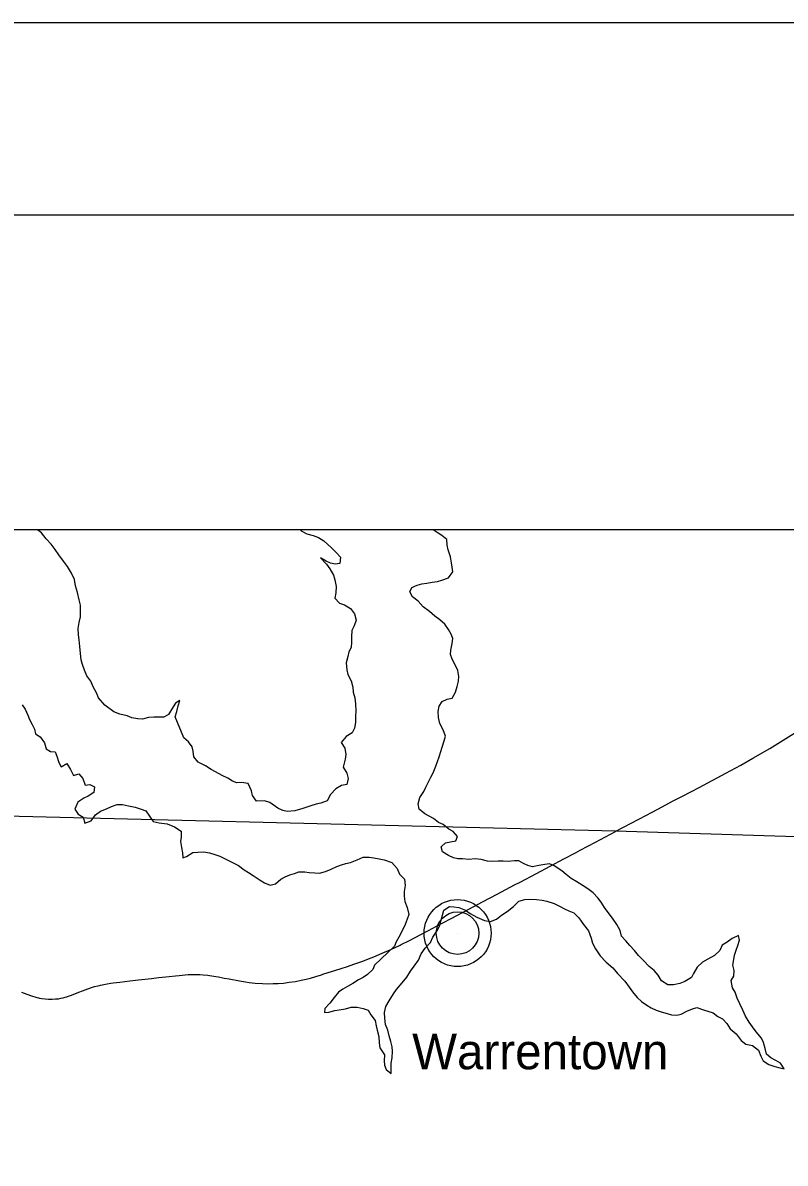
# Model space of a CAD drawing. Extents: x -29.6 to 34, y 0 to 22.
# Drawn here: x 8.82 to 10.805, y 19.03 to 22 of the extents above; entities that cross this region are included whole.
import ezdxf

# ---------------------------------------------------------------- set-up
doc = ezdxf.new("R2010")
doc.units = 0
for name, color, linetype in [('GM_X_Major_Lake', 7, 'Continuous'), ('GM_X_Township', 7, 'Continuous'), ('GM_X_Unincorporated', 7, 'Continuous'), ('GM_X_Unincorporated_Location', 7, 'Continuous'), ('GM_X_Unincorporated_Text', 7, 'Continuous'), ('GM_X_US_Route', 7, 'Continuous'), ('SH_Border', 7, 'Continuous'), ('SH_Cut_Line', 7, 'Continuous'), ('SH_Text', 7, 'Continuous')]:
    doc.layers.add(name, color=color, linetype=linetype)

msp = doc.modelspace()

# ---------------------------------------------------------------- linework, layer by layer
at = {"layer": 'GM_X_Major_Lake'}
for points in [[(9.2387, 20.1379), (9.2161, 20.1924), (9.2209, 20.2062), (9.2243, 20.2208), (9.2291, 20.2355), (9.2172, 20.2279), (9.2071, 20.2118), (9.1988, 20.1985), (9.1869, 20.1917), (9.1749, 20.1921), (9.1607, 20.1915), (9.1474, 20.1905), (9.1315, 20.1864), (9.1196, 20.1872), (9.104, 20.1902), (9.0912, 20.1955), (9.0721, 20.1998), (9.057, 20.2059), (9.0334, 20.2226), (9.0173, 20.242), (9.0119, 20.2553), (9.0029, 20.2704), (8.9966, 20.2854), (8.9864, 20.2996), (8.9805, 20.3142), (8.9751, 20.3284), (8.9719, 20.3412), (8.9696, 20.3576), (8.9681, 20.3758), (8.9662, 20.3927), (8.9652, 20.406), (8.9642, 20.4224), (8.9664, 20.4385), (8.9698, 20.4531), (8.9696, 20.4833), (8.9668, 20.4975), (8.9618, 20.5162), (8.9568, 20.5339), (8.9541, 20.5503), (8.9469, 20.5667), (8.9361, 20.5844), (8.9258, 20.5981), (8.9138, 20.6144), (8.9044, 20.6281), (8.8937, 20.6418), (8.8803, 20.6564), (8.8682, 20.6714), (8.8577, 20.6798)], [(9.5426, 20.6798), (9.5442, 20.6773), (9.5594, 20.6694), (9.5758, 20.6646), (9.5901, 20.6594), (9.6039, 20.6511), (9.6232, 20.6326), (9.6357, 20.6203), (9.6469, 20.6084), (9.6453, 20.5919), (9.6329, 20.59), (9.6213, 20.5926), (9.6093, 20.5983), (9.595, 20.6066)], [(9.9251, 20.2383), (9.9375, 20.2411), (9.9463, 20.2567), (9.9506, 20.2719), (9.9545, 20.2852), (9.9552, 20.2972), (9.9529, 20.3136), (9.9465, 20.326), (9.9375, 20.3428), (9.9334, 20.3548), (9.9342, 20.3664), (9.9376, 20.3837), (9.9397, 20.3962), (9.9351, 20.4077), (9.9279, 20.4201), (9.9185, 20.4338), (9.9055, 20.4452), (9.8925, 20.4549), (9.8791, 20.4668), (9.8626, 20.4791), (9.8496, 20.4941), (9.8348, 20.5051), (9.8271, 20.5183), (9.8328, 20.5295), (9.8465, 20.5358), (9.8589, 20.5386), (9.8722, 20.5409), (9.886, 20.5433), (9.8997, 20.5452), (9.9112, 20.5488), (9.928, 20.5547), (9.9395, 20.5699), (9.938, 20.5819), (9.9361, 20.5939), (9.9338, 20.609), (9.9274, 20.6272), (9.9246, 20.64), (9.9236, 20.6547), (9.9106, 20.6652), (9.8986, 20.6722), (9.888, 20.6798)], [(9.595, 20.6066), (9.6103, 20.5898), (9.6192, 20.5784), (9.6287, 20.5616), (9.6319, 20.5496), (9.6356, 20.5318), (9.6349, 20.5158), (9.6324, 20.5012), (9.6445, 20.4884), (9.6578, 20.484), (9.673, 20.4748), (9.6834, 20.4607), (9.6875, 20.4447), (9.6827, 20.4296), (9.6766, 20.4175), (9.6755, 20.4011), (9.6756, 20.3873), (9.6748, 20.3735), (9.6691, 20.3619), (9.6657, 20.3499), (9.6619, 20.3334), (9.6634, 20.3148), (9.6657, 20.3032), (9.6747, 20.286), (9.6793, 20.2696), (9.6803, 20.2567), (9.6844, 20.2416), (9.6864, 20.2265), (9.6865, 20.207), (9.6858, 20.195), (9.6864, 20.1781), (9.6838, 20.1634), (9.6777, 20.1509), (9.6618, 20.141), (9.6491, 20.1253), (9.6586, 20.1112), (9.6605, 20.0943), (9.6593, 20.0823), (9.6541, 20.0618), (9.6632, 20.0454), (9.6673, 20.0321), (9.6639, 20.0161), (9.6492, 20.0133), (9.6347, 20.0052), (9.6206, 19.9904), (9.6119, 19.9739), (9.5959, 19.968), (9.584, 19.9652), (9.5694, 19.9611), (9.549, 19.9534), (9.5282, 19.9479), (9.5082, 19.9459), (9.4966, 19.9489), (9.4837, 19.955), (9.4627, 19.9691), (9.4489, 19.9739), (9.4285, 19.9732), (9.4177, 19.9878), (9.4149, 19.9998), (9.4063, 20.0193), (9.389, 20.0218), (9.3774, 20.0208), (9.3654, 20.0247), (9.3538, 20.0331), (9.3391, 20.0396), (9.3212, 20.0497), (9.3101, 20.0558), (9.2953, 20.0646), (9.2766, 20.0742), (9.2654, 20.0883), (9.263, 20.103), (9.2611, 20.1145), (9.2508, 20.1278), (9.2387, 20.1379)], [(10.6686, 19.5462), (10.6707, 19.5609), (10.6728, 19.572), (10.6776, 19.585), (10.6819, 19.597), (10.6858, 19.6113), (10.683, 19.6228), (10.6671, 19.6156), (10.6534, 19.6057), (10.6406, 19.5976), (10.6345, 19.5837), (10.6209, 19.5707), (10.6036, 19.5617), (10.5895, 19.5536), (10.5759, 19.5406), (10.5663, 19.5245), (10.5606, 19.5133), (10.5434, 19.5034), (10.5305, 19.4979), (10.5137, 19.4947), (10.499, 19.4946), (10.483, 19.5051), (10.4744, 19.5201), (10.4636, 19.5316), (10.4511, 19.5426), (10.4349, 19.5589), (10.4233, 19.5713), (10.4121, 19.5836), (10.3999, 19.5973), (10.3901, 19.6088), (10.3789, 19.6211), (10.3752, 19.6358), (10.3666, 19.6517), (10.3549, 19.6681), (10.3436, 19.6831), (10.3342, 19.6959), (10.3256, 19.7096), (10.3171, 19.7215), (10.305, 19.7343), (10.2907, 19.7444), (10.2791, 19.7528), (10.2625, 19.7624), (10.2474, 19.7712), (10.2344, 19.7822), (10.2232, 19.7914), (10.2031, 19.8046), (10.1915, 19.8094), (10.1791, 19.808), (10.1636, 19.8052), (10.1467, 19.8019), (10.1347, 19.8054), (10.1231, 19.8102), (10.1111, 19.8172), (10.1, 19.8171), (10.0835, 19.8161), (10.0702, 19.8168), (10.0573, 19.8167), (10.0405, 19.8161), (10.0294, 19.8169), (10.0133, 19.8208), (9.9978, 19.8229), (9.9814, 19.8214), (9.9649, 19.8226), (9.9525, 19.8225), (9.9414, 19.8255), (9.9284, 19.8312), (9.9128, 19.8413), (9.9087, 19.8541), (9.9201, 19.864), (9.933, 19.8668), (9.9472, 19.8696), (9.952, 19.8807), (9.9407, 19.8935), (9.9291, 19.9001), (9.9144, 19.9124), (9.9023, 19.9172), (9.8889, 19.9282), (9.8778, 19.9339), (9.8662, 19.94), (9.8514, 19.9519), (9.849, 19.9661), (9.8533, 19.9826), (9.8638, 19.9978), (9.8691, 20.0098), (9.876, 20.0232), (9.8821, 20.0353), (9.8887, 20.0464), (9.8956, 20.0643), (9.8995, 20.0763), (9.9043, 20.0884), (9.9082, 20.1022), (9.9116, 20.1138), (9.9168, 20.1298), (9.9207, 20.1423), (9.9139, 20.1591), (9.9053, 20.1755), (9.902, 20.191), (9.901, 20.2061), (9.9035, 20.2203), (9.9114, 20.2329), (9.9251, 20.2383)], [(8.8181, 20.2242), (8.8257, 20.2127), (8.8329, 20.1967), (8.837, 20.1852), (8.8442, 20.1728), (8.8505, 20.16), (8.8528, 20.148), (8.8652, 20.1401), (8.8764, 20.1251), (8.8805, 20.1091), (8.8921, 20.1021), (8.904, 20.1013), (8.9085, 20.0898), (8.9135, 20.0738), (8.9194, 20.0619), (8.9348, 20.0713), (8.9442, 20.0558), (8.9519, 20.0399), (8.966, 20.0444), (8.9758, 20.0316), (8.9826, 20.0143), (8.9945, 20.0162), (9.0061, 20.01), (9.0049, 19.9954), (8.9903, 19.9855), (8.9784, 19.9805), (8.963, 19.9706), (8.9551, 19.9524), (8.9641, 19.9391), (8.977, 19.9312), (8.9811, 19.9157), (8.9974, 19.9216), (9.0093, 19.9372), (9.0225, 19.9471), (9.0375, 19.953), (9.0507, 19.9588), (9.0658, 19.9638), (9.0795, 19.9644), (9.0946, 19.9609), (9.1123, 19.957), (9.1283, 19.9523), (9.1403, 19.9475), (9.1497, 19.9338), (9.1595, 19.9196), (9.1746, 19.9162), (9.1955, 19.9141), (9.2146, 19.9062), (9.2323, 19.8952), (9.2325, 19.8793), (9.2308, 19.8681), (9.2326, 19.8526), (9.2354, 19.8384), (9.2364, 19.8251), (9.246, 19.8286)], [(9.246, 19.8286), (9.2623, 19.8389), (9.2756, 19.8404), (9.2912, 19.8409), (9.3063, 19.8384), (9.3201, 19.8336), (9.3326, 19.8293), (9.3656, 19.8131), (9.3812, 19.8053), (9.3964, 19.7943), (9.4076, 19.7868), (9.4196, 19.7794), (9.4379, 19.7675), (9.4491, 19.76), (9.4643, 19.7544), (9.478, 19.7576), (9.4916, 19.7702), (9.5031, 19.7761), (9.5151, 19.781), (9.527, 19.7843), (9.5385, 19.7892), (9.5541, 19.7885), (9.5656, 19.7872), (9.5799, 19.7865), (9.5927, 19.7857), (9.6078, 19.7894), (9.6228, 19.7957), (9.6374, 19.803), (9.6494, 19.8071), (9.6609, 19.8103), (9.6728, 19.8135), (9.6901, 19.8199), (9.706, 19.8275), (9.722, 19.8268), (9.7336, 19.8256), (9.7478, 19.823), (9.7611, 19.8205), (9.7803, 19.8135), (9.7947, 19.7976), (9.8006, 19.783), (9.8136, 19.7698), (9.815, 19.7529), (9.8125, 19.7378), (9.8126, 19.7253), (9.8145, 19.7115), (9.8209, 19.696), (9.8246, 19.6774), (9.8208, 19.6654), (9.8151, 19.6515), (9.8068, 19.6337), (9.7985, 19.6185), (9.792, 19.6069), (9.7872, 19.5957), (9.7357, 19.5459), (9.7314, 19.5343), (9.7173, 19.5213), (9.7058, 19.5137), (9.6935, 19.5073), (9.6789, 19.4979), (9.6652, 19.4902), (9.6533, 19.483), (9.6418, 19.4758), (9.6304, 19.4615), (9.6194, 19.4467), (9.6063, 19.4332), (9.605, 19.4221), (9.617, 19.4236), (9.6321, 19.4277), (9.6436, 19.4296), (9.6604, 19.4324), (9.675, 19.4361), (9.6901, 19.4366), (9.7057, 19.4332), (9.7186, 19.4284), (9.7259, 19.4165), (9.7375, 19.4019), (9.7399, 19.3881), (9.7427, 19.3762), (9.7464, 19.3597), (9.7479, 19.3437), (9.7497, 19.3309), (9.7619, 19.3123), (9.7607, 19.2967), (9.7617, 19.2856), (9.7658, 19.2741), (9.7792, 19.264), (9.7791, 19.2764), (9.7786, 19.2902), (9.7811, 19.3049), (9.7827, 19.3218), (9.7817, 19.3329), (9.778, 19.3467), (9.7739, 19.3617), (9.7706, 19.3768), (9.7643, 19.3915), (9.7623, 19.4074), (9.7618, 19.4226), (9.7647, 19.4381), (9.7735, 19.4533), (9.7853, 19.4708), (9.7932, 19.4828)], [(9.7932, 19.4828), (9.8077, 19.4994), (9.8199, 19.5146), (9.8296, 19.5298), (9.8392, 19.5433), (9.8497, 19.5585), (9.8571, 19.575), (9.8676, 19.5897), (9.8813, 19.605), (9.8873, 19.6184), (9.8979, 19.634), (9.9053, 19.6492), (9.9078, 19.6608), (9.913, 19.6764), (9.9164, 19.6888), (9.931, 19.6987), (9.9421, 19.6979), (9.955, 19.6958), (9.9724, 19.6893), (9.9845, 19.6805), (10.0019, 19.6704), (10.0215, 19.6617), (10.0375, 19.6592), (10.053, 19.666), (10.0658, 19.6759), (10.0808, 19.6858), (10.0971, 19.6988), (10.1116, 19.7123), (10.1266, 19.7168), (10.1386, 19.7174), (10.1573, 19.7171), (10.1724, 19.715), (10.184, 19.7129), (10.2031, 19.7064), (10.2192, 19.6989), (10.2303, 19.6924), (10.2415, 19.6876), (10.2544, 19.6823), (10.2678, 19.6687), (10.28, 19.6519), (10.293, 19.6351), (10.2994, 19.6165), (10.3035, 19.6032), (10.3112, 19.5886), (10.3229, 19.5704), (10.3391, 19.5532), (10.3557, 19.5387), (10.3682, 19.5237), (10.3871, 19.5038), (10.3987, 19.4888), (10.4069, 19.4764), (10.419, 19.4619), (10.4306, 19.4509), (10.4445, 19.4416), (10.4556, 19.4346), (10.469, 19.429), (10.4815, 19.4246), (10.4975, 19.4203), (10.5087, 19.4168), (10.5229, 19.4156), (10.5344, 19.4184), (10.5485, 19.4256), (10.5631, 19.432), (10.5746, 19.4356), (10.5925, 19.4291), (10.6169, 19.4218), (10.6295, 19.4125), (10.642, 19.4064), (10.6527, 19.394), (10.6617, 19.3803), (10.6774, 19.3667), (10.69, 19.3495), (10.7025, 19.3398), (10.7199, 19.3364), (10.7355, 19.3245), (10.7415, 19.3085), (10.7478, 19.2966), (10.7625, 19.2869), (10.7781, 19.2822), (10.791, 19.2783), (10.8021, 19.2757), (10.7922, 19.2907), (10.7806, 19.2978), (10.7677, 19.3043), (10.7565, 19.3136), (10.7524, 19.3291), (10.7487, 19.3446), (10.7428, 19.3561), (10.7289, 19.372), (10.7194, 19.3848), (10.7109, 19.3976), (10.7014, 19.4131), (10.6946, 19.4282), (10.6869, 19.445), (10.6801, 19.4601), (10.6742, 19.4751), (10.6678, 19.4871), (10.6641, 19.5057), (10.6711, 19.5169), (10.6723, 19.5316), (10.6686, 19.5462)]]:
    msp.add_lwpolyline(points, dxfattribs=at)
at = {"layer": 'GM_X_Township'}
msp.add_lwpolyline([(13.2018, 20.6798), (13.1972, 20.4897), (13.1757, 19.8128), (12.0094, 19.8432), (11.9667, 19.8448), (10.3631, 19.8945), (8.3857, 19.9434), (7.5502, 19.9616), (7.2204, 19.9686), (7.2242, 20.1907), (7.2354, 20.6798)], dxfattribs=at)
at = {"layer": 'GM_X_Unincorporated'}
for radius in [0.0872, 0.0553]:
    msp.add_circle((9.9518, 19.6293), radius, dxfattribs=at)
at = {"layer": 'GM_X_Unincorporated_Location'}
msp.add_line((9.9518, 19.6293), (9.9518, 19.6293), dxfattribs=at)
at = {"layer": 'GM_X_US_Route'}
for points in [[(10.3643, 19.8944), (10.4436, 19.9366), (10.4565, 19.9433), (10.4752, 19.953), (10.5118, 19.9726), (10.5356, 19.9852), (10.5607, 19.9984), (10.5807, 20.0089), (10.6502, 20.0457), (10.6891, 20.067), (10.7209, 20.0848), (10.7649, 20.1105), (10.7855, 20.1229), (10.8596, 20.1692)], [(9.6012, 19.5221), (9.6153, 19.5264), (9.6348, 19.5325), (9.6488, 19.5371), (9.6656, 19.5426), (9.6814, 19.5481), (9.7055, 19.5566), (9.7203, 19.5621), (9.7334, 19.5673), (9.7556, 19.5769), (9.7779, 19.5866), (9.8024, 19.5982), (9.8046, 19.5993), (9.8266, 19.6103), (9.8563, 19.6257), (9.8893, 19.643), (9.8956, 19.6463), (9.9349, 19.6671), (9.9809, 19.6916), (10.0171, 19.7109), (10.0552, 19.7309), (10.1003, 19.7546), (10.1144, 19.7621), (10.1569, 19.7846), (10.2283, 19.8223), (10.2585, 19.8384), (10.2709, 19.845), (10.3112, 19.8662), (10.3633, 19.8939), (10.3643, 19.8944)], [(8.816, 19.4758), (8.8231, 19.4731), (8.83, 19.4704), (8.8424, 19.466), (8.8534, 19.4625), (8.8563, 19.4616), (8.8604, 19.4606), (8.8631, 19.4601), (8.8697, 19.459), (8.878, 19.4579), (8.887, 19.4574), (8.896, 19.4571), (8.905, 19.4577), (8.9125, 19.4585), (8.9191, 19.4596), (8.9246, 19.461), (8.9304, 19.4625), (8.9341, 19.4635), (8.9365, 19.4643), (8.944, 19.467), (8.9468, 19.468), (8.9655, 19.4754), (8.975, 19.4791), (8.9893, 19.4843), (9.0012, 19.4881), (9.0069, 19.4899), (9.0156, 19.4921), (9.022, 19.4935), (9.0391, 19.497), (9.0493, 19.4985), (9.0552, 19.4994), (9.0726, 19.5019), (9.0985, 19.5049), (9.121, 19.5075), (9.1549, 19.5113), (9.1673, 19.5127), (9.1737, 19.5134), (9.201, 19.5163), (9.2176, 19.5182), (9.2271, 19.5193), (9.2429, 19.5207), (9.2506, 19.5213), (9.2625, 19.5217), (9.2664, 19.5217), (9.2741, 19.5216), (9.281, 19.5214), (9.2897, 19.5207), (9.3016, 19.5197), (9.3061, 19.519), (9.3118, 19.5183), (9.3226, 19.5164), (9.3292, 19.5152), (9.3442, 19.5123), (9.3568, 19.5098), (9.3838, 19.505), (9.3999, 19.5021), (9.4096, 19.5007), (9.4251, 19.499), (9.4437, 19.4979), (9.4575, 19.4975), (9.472, 19.4977), (9.4851, 19.4982), (9.4984, 19.4993), (9.5134, 19.5012), (9.5299, 19.5036), (9.5444, 19.5064), (9.5577, 19.5093), (9.5689, 19.5123), (9.5824, 19.5161), (9.5977, 19.521), (9.6012, 19.5221)]]:
    msp.add_lwpolyline(points, dxfattribs=at)
at = {"layer": 'SH_Border'}
msp.add_lwpolyline([(1.5, 21.5), (33.5, 21.5), (33.5, 0.5), (1.5, 0.5)], close=True, dxfattribs=at)
at = {"layer": 'SH_Cut_Line'}
msp.add_lwpolyline([(0, 0), (34, 0), (34, 22), (0, 22)], close=True, dxfattribs=at)
at = {"layer": 'SH_Text'}
msp.add_line((20.8747, 20.6798), (2.5893, 20.6798), dxfattribs=at)

# ---------------------------------------------------------------- texts
at = {"layer": 'GM_X_Unincorporated_Text'}
msp.add_text('Warrentown', height=0.09255, rotation=0, dxfattribs=at).set_placement((9.8336, 19.2747))

doc.saveas('drawing.dxf')
